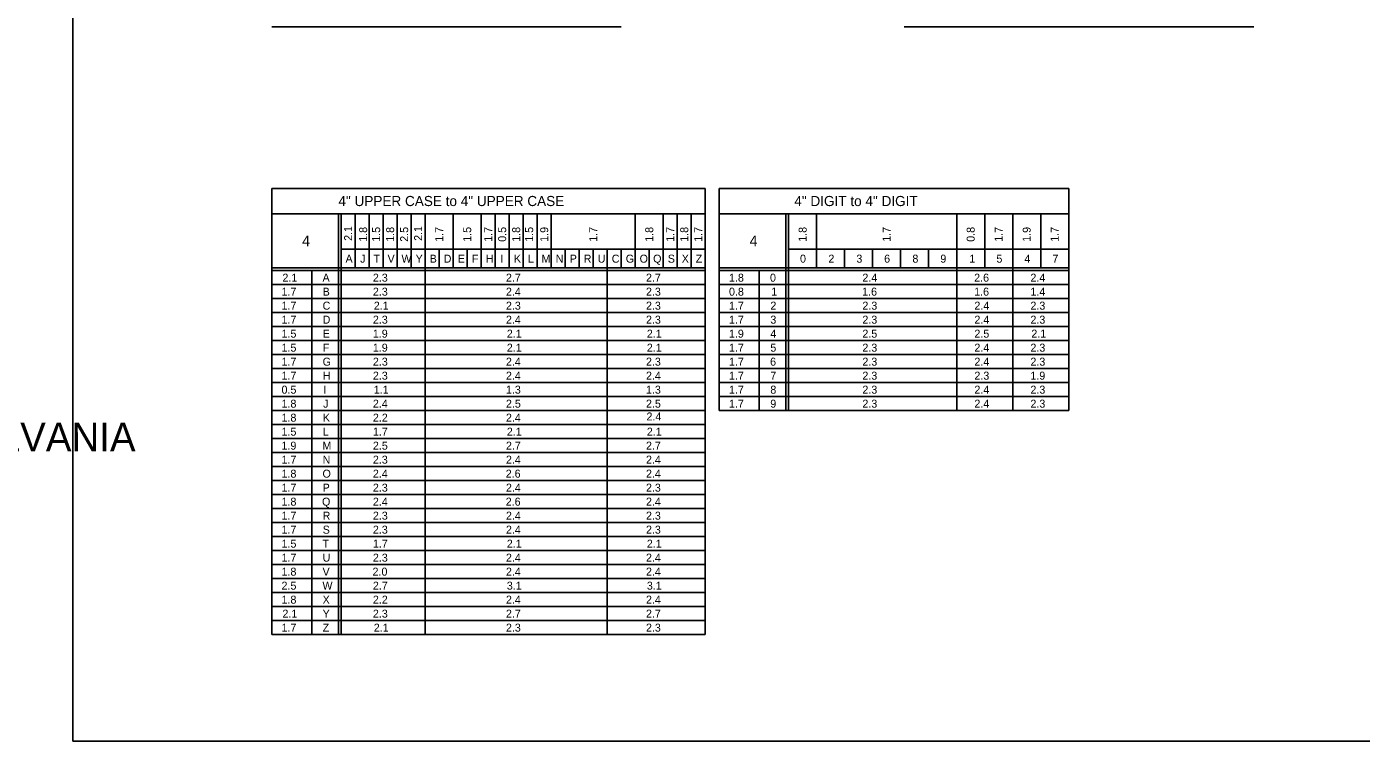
# Model space of a CAD drawing. Extents: x 638421 to 641849, y 297270 to 299646.
# Drawn here: x 640967 to 641467, y 299067 to 299335 of the extents above; entities that cross this region are included whole.
import ezdxf

# ---------------------------------------------------------------- set-up
doc = ezdxf.new("R2010")
doc.units = 0
doc.layers.add('1', color=7, linetype='Continuous')
doc.layers.add('2', color=7, linetype='Continuous')

msp = doc.modelspace()

# ---------------------------------------------------------------- linework, layer by layer
at = {"layer": '1'}
for p, q in [((640984.31, 299630.63), (640984.31, 299066.63)), ((641770.31, 299066.63), (640984.31, 299066.63)), ((640984.31, 299066.63), (641570.31, 299066.63))]:
    msp.add_line(p, q, dxfattribs=at)
at = {"layer": '2'}
for p, q in [((641058.94, 299334.63), (641189.94, 299334.63)), ((641296.06, 299334.63), (641427.06, 299334.63)), ((641221.44, 299274), (641058.94, 299274)), ((641058.94, 299274), (641058.94, 299106.63)), ((641221.44, 299274), (641221.44, 299106.63)), ((641357.69, 299274), (641226.69, 299274)), ((641226.69, 299274), (641226.69, 299190.63)), ((641357.69, 299190.63), (641357.69, 299274)), ((641058.94, 299264.5), (641221.44, 299264.5)), ((641083.94, 299264.5), (641083.94, 299106.63)), ((641084.94, 299264.5), (641084.94, 299106.63)), ((641090.19, 299264.5), (641090.19, 299244.13)), ((641095.44, 299264.5), (641095.44, 299244.13)), ((641100.69, 299264.5), (641100.69, 299244.13)), ((641105.94, 299264.5), (641105.94, 299244.13)), ((641111.19, 299264.5), (641111.19, 299244.13)), ((641116.44, 299264.5), (641116.44, 299106.63)), ((641126.94, 299264.5), (641126.94, 299244.13)), ((641137.44, 299264.5), (641137.44, 299244.13)), ((641142.69, 299264.5), (641142.69, 299244.13)), ((641147.94, 299264.5), (641147.94, 299244.13)), ((641153.19, 299264.5), (641153.19, 299244.13)), ((641158.44, 299264.5), (641158.44, 299244.13)), ((641163.69, 299264.5), (641163.69, 299244.13)), ((641195.19, 299264.5), (641195.19, 299244.13)), ((641205.69, 299264.5), (641205.69, 299244.13)), ((641210.94, 299264.5), (641210.94, 299244.13)), ((641216.19, 299264.5), (641216.19, 299244.13)), ((641226.69, 299264.5), (641357.69, 299264.5)), ((641251.69, 299264.5), (641251.69, 299190.63)), ((641252.69, 299264.5), (641252.69, 299190.63)), ((641263.19, 299264.5), (641263.19, 299244.13)), ((641315.69, 299264.5), (641315.69, 299190.63)), ((641326.19, 299264.5), (641326.19, 299244.13)), ((641336.69, 299264.5), (641336.69, 299190.63)), ((641347.19, 299264.5), (641347.19, 299244.13)), ((641084.94, 299251.13), (641221.44, 299251.13)), ((641121.69, 299251.13), (641121.69, 299244.13)), ((641132.19, 299251.13), (641132.19, 299244.13)), ((641168.94, 299251.13), (641168.94, 299244.13)), ((641174.19, 299251.13), (641174.19, 299244.13)), ((641179.44, 299251.13), (641179.44, 299244.13)), ((641179.44, 299251.13), (641179.44, 299244.13)), ((641184.69, 299251.13), (641184.69, 299106.63)), ((641189.94, 299251.13), (641189.94, 299244.13)), ((641200.44, 299251.13), (641200.44, 299244.13)), ((641252.69, 299251.13), (641357.69, 299251.13)), ((641273.69, 299251.13), (641273.69, 299244.13)), ((641284.19, 299251.13), (641284.19, 299244.13)), ((641294.69, 299251.13), (641294.69, 299244.13)), ((641305.19, 299251.13), (641305.19, 299244.13)), ((641221.44, 299244.13), (641058.94, 299244.13)), ((641357.69, 299244.13), (641226.69, 299244.13)), ((641221.44, 299243.13), (641058.94, 299243.13)), ((641073.94, 299243.13), (641073.94, 299106.63)), ((641357.69, 299243.13), (641226.69, 299243.13)), ((641241.69, 299243.13), (641241.69, 299190.63)), ((641221.44, 299237.88), (641058.94, 299237.88)), ((641357.69, 299237.88), (641226.69, 299237.88)), ((641221.44, 299232.63), (641058.94, 299232.63)), ((641357.69, 299232.63), (641226.69, 299232.63)), ((641221.44, 299227.38), (641058.94, 299227.38)), ((641357.69, 299227.38), (641226.69, 299227.38)), ((641221.44, 299222.13), (641058.94, 299222.13)), ((641357.69, 299222.13), (641226.69, 299222.13)), ((641221.44, 299216.88), (641058.94, 299216.88)), ((641357.69, 299216.88), (641226.69, 299216.88)), ((641221.44, 299211.63), (641058.94, 299211.63)), ((641357.69, 299211.63), (641226.69, 299211.63)), ((641221.44, 299206.38), (641058.94, 299206.38)), ((641357.69, 299206.38), (641226.69, 299206.38)), ((641221.44, 299201.13), (641058.94, 299201.13)), ((641357.69, 299201.13), (641226.69, 299201.13)), ((641221.44, 299195.88), (641058.94, 299195.88)), ((641357.69, 299195.88), (641226.69, 299195.88)), ((641221.44, 299190.63), (641058.94, 299190.63)), ((641226.69, 299190.63), (641357.69, 299190.63)), ((641221.44, 299185.38), (641058.94, 299185.38)), ((641221.44, 299180.13), (641058.94, 299180.13)), ((641221.44, 299174.88), (641058.94, 299174.88)), ((641221.44, 299169.63), (641058.94, 299169.63)), ((641221.44, 299164.38), (641058.94, 299164.38)), ((641221.44, 299159.13), (641058.94, 299159.13)), ((641221.44, 299153.88), (641058.94, 299153.88)), ((641221.44, 299148.63), (641058.94, 299148.63)), ((641221.44, 299143.38), (641058.94, 299143.38)), ((641221.44, 299138.13), (641058.94, 299138.13)), ((641221.44, 299132.88), (641058.94, 299132.88)), ((641221.44, 299127.63), (641058.94, 299127.63)), ((641221.44, 299122.38), (641058.94, 299122.38)), ((641221.44, 299117.13), (641058.94, 299117.13)), ((641221.44, 299111.88), (641058.94, 299111.88)), ((641058.94, 299106.63), (641058.94, 299106.63)), ((641058.94, 299106.63), (641221.44, 299106.63))]:
    msp.add_line(p, q, dxfattribs=at)

# ---------------------------------------------------------------- texts
at = {"layer": '1'}
msp.add_text('COMMONWEALTH OF PENNSYLVANIA', height=10.7828, dxfattribs=at).set_placement((640741.9, 299175.36))
at = {"layer": '2'}
for s, height, p in [('4" UPPER CASE to 4" UPPER CASE', 3.8, (641083.92, 299267.35)), ('4" DIGIT to 4" DIGIT', 3.8, (641254.83, 299267.35)), ('4', 4, (641070.3, 299252.31)), ('4', 4, (641238.05, 299252.31)), ('A', 3, (641086.58, 299246.13)), ('J', 3, (641092.07, 299246.13)), ('T', 3, (641097.07, 299246.13)), ('V', 3, (641102.33, 299246.13)), ('W', 3, (641107.56, 299246.13)), ('Y', 3, (641112.87, 299246.13)), ('B', 3, (641118.13, 299246.13)), ('D', 3, (641123.38, 299246.13)), ('E', 3, (641128.64, 299246.13)), ('F', 3, (641133.95, 299246.13)), ('H', 3, (641139.21, 299246.13)), ('I', 3, (641144.63, 299246.13)), ('K', 3, (641149.71, 299246.13)), ('L', 3, (641154.96, 299246.13)), ('M', 3, (641160.06, 299246.13)), ('N', 3, (641165.38, 299246.13)), ('P', 3, (641170.63, 299246.13)), ('R', 3, (641175.88, 299246.13)), ('U', 3, (641181.12, 299246.13)), ('C', 3, (641186.38, 299246.13)), ('G', 3, (641191.63, 299246.13)), ('O', 3, (641196.83, 299246.13)), ('Q', 3, (641201.9, 299246.13)), ('S', 3, (641207.39, 299246.13)), ('X', 3, (641212.62, 299246.13)), ('Z', 3, (641217.88, 299246.13)), ('0', 3, (641256.96, 299246.13)), ('2', 3, (641267.59, 299246.13)), ('3', 3, (641278.09, 299246.13)), ('6', 3, (641288.5, 299246.13)), ('8', 3, (641299.09, 299246.13)), ('9', 3, (641309.57, 299246.13)), ('1', 3, (641320.43, 299246.13)), ('5', 3, (641330.59, 299246.13)), ('4', 3, (641341.09, 299246.13)), ('7', 3, (641351.59, 299246.13)), ('2.1', 3, (641062.93, 299239)), ('A', 3, (641077.96, 299239)), ('2.3', 3, (641096.84, 299239)), ('2.7', 3, (641146.71, 299239)), ('2.7', 3, (641199.21, 299239)), ('1.8', 3, (641230.34, 299239)), ('0', 3, (641245.71, 299239)), ('2.4', 3, (641280.34, 299239)), ('2.6', 3, (641322.25, 299239)), ('2.4', 3, (641343.34, 299239)), ('1.7', 3, (641062.59, 299233.75)), ('B', 3, (641078, 299233.75)), ('2.3', 3, (641096.84, 299233.75)), ('2.4', 3, (641146.71, 299233.75)), ('2.3', 3, (641199.21, 299233.75)), ('0.8', 3, (641230.34, 299233.75)), ('1', 3, (641246.18, 299233.75)), ('1.6', 3, (641280.25, 299233.75)), ('1.6', 3, (641322.25, 299233.75)), ('1.4', 3, (641343.34, 299233.75)), ('1.7', 3, (641062.59, 299228.5)), ('C', 3, (641078, 299228.5)), ('2.1', 3, (641097.18, 299228.5)), ('2.3', 3, (641146.71, 299228.5)), ('2.3', 3, (641199.21, 299228.5)), ('1.7', 3, (641230.34, 299228.5)), ('2', 3, (641245.84, 299228.5)), ('2.3', 3, (641280.34, 299228.5)), ('2.4', 3, (641322.34, 299228.5)), ('2.3', 3, (641343.34, 299228.5)), ('1.7', 3, (641062.59, 299223.25)), ('D', 3, (641078, 299223.25)), ('2.3', 3, (641096.84, 299223.25)), ('2.4', 3, (641146.71, 299223.25)), ('2.3', 3, (641199.21, 299223.25)), ('1.7', 3, (641230.34, 299223.25)), ('3', 3, (641245.84, 299223.25)), ('2.3', 3, (641280.34, 299223.25)), ('2.4', 3, (641322.34, 299223.25)), ('2.3', 3, (641343.34, 299223.25)), ('1.5', 3, (641062.59, 299218)), ('E', 3, (641078.02, 299218)), ('1.9', 3, (641096.82, 299218)), ('2.1', 3, (641147.05, 299218)), ('2.1', 3, (641199.55, 299218)), ('1.9', 3, (641230.32, 299218)), ('4', 3, (641245.84, 299218)), ('2.5', 3, (641280.34, 299218)), ('2.5', 3, (641322.34, 299218)), ('2.1', 3, (641343.68, 299218)), ('1.5', 3, (641062.59, 299212.75)), ('F', 3, (641078.07, 299212.75)), ('1.9', 3, (641096.82, 299212.75)), ('2.1', 3, (641147.05, 299212.75)), ('2.1', 3, (641199.55, 299212.75)), ('1.7', 3, (641230.34, 299212.75)), ('5', 3, (641245.84, 299212.75)), ('2.3', 3, (641280.34, 299212.75)), ('2.4', 3, (641322.34, 299212.75)), ('2.3', 3, (641343.34, 299212.75)), ('1.7', 3, (641062.59, 299207.5)), ('G', 3, (641078, 299207.5)), ('2.3', 3, (641096.84, 299207.5)), ('2.4', 3, (641146.71, 299207.5)), ('2.3', 3, (641199.21, 299207.5)), ('1.7', 3, (641230.34, 299207.5)), ('6', 3, (641245.75, 299207.5)), ('2.3', 3, (641280.34, 299207.5)), ('2.4', 3, (641322.34, 299207.5)), ('2.3', 3, (641343.34, 299207.5)), ('1.7', 3, (641062.59, 299202.25)), ('H', 3, (641078.09, 299202.25)), ('2.3', 3, (641096.84, 299202.25)), ('2.4', 3, (641146.71, 299202.25)), ('2.4', 3, (641199.21, 299202.25)), ('1.7', 3, (641230.34, 299202.25)), ('7', 3, (641245.84, 299202.25)), ('2.3', 3, (641280.34, 299202.25)), ('2.3', 3, (641322.34, 299202.25)), ('1.9', 3, (641343.32, 299202.25)), ('0.5', 3, (641062.59, 299197)), ('I', 3, (641078.25, 299197)), ('1.1', 3, (641097.18, 299197)), ('1.3', 3, (641146.71, 299197)), ('1.3', 3, (641199.21, 299197)), ('1.7', 3, (641230.34, 299197)), ('8', 3, (641245.84, 299197)), ('2.3', 3, (641280.34, 299197)), ('2.4', 3, (641322.34, 299197)), ('2.3', 3, (641343.34, 299197)), ('1.8', 3, (641062.59, 299191.75)), ('J', 3, (641078.19, 299191.75)), ('2.4', 3, (641096.84, 299191.75)), ('2.5', 3, (641146.71, 299191.75)), ('2.5', 3, (641199.21, 299191.75)), ('1.7', 3, (641230.34, 299191.75)), ('9', 3, (641245.82, 299191.75)), ('2.3', 3, (641280.34, 299191.75)), ('2.4', 3, (641322.34, 299191.75)), ('2.3', 3, (641343.34, 299191.75)), ('1.8', 3, (641062.59, 299186.5)), ('K', 3, (641078.09, 299186.5)), ('2.2', 3, (641096.84, 299186.5)), ('2.4', 3, (641146.71, 299186.5)), ('2.4', 3, (641199.4, 299186.94)), ('1.5', 3, (641062.59, 299181.25)), ('L', 3, (641078.09, 299181.25)), ('1.7', 3, (641096.84, 299181.25)), ('2.1', 3, (641147.05, 299181.25)), ('2.1', 3, (641199.55, 299181.25)), ('1.9', 3, (641062.57, 299176)), ('M', 3, (641077.93, 299176)), ('2.5', 3, (641096.84, 299176)), ('2.7', 3, (641146.71, 299176)), ('2.7', 3, (641199.21, 299176)), ('1.7', 3, (641062.59, 299170.75)), ('N', 3, (641078, 299170.75)), ('2.3', 3, (641096.84, 299170.75)), ('2.4', 3, (641146.71, 299170.75)), ('2.4', 3, (641199.21, 299170.75)), ('1.8', 3, (641062.59, 299165.5)), ('O', 3, (641077.96, 299165.5)), ('2.4', 3, (641096.84, 299165.5)), ('2.6', 3, (641146.63, 299165.5)), ('2.4', 3, (641199.21, 299165.5)), ('1.7', 3, (641062.59, 299160.25)), ('P', 3, (641078, 299160.25)), ('2.3', 3, (641096.84, 299160.25)), ('2.4', 3, (641146.71, 299160.25)), ('2.3', 3, (641199.21, 299160.25)), ('1.8', 3, (641062.59, 299155)), ('Q', 3, (641077.78, 299155)), ('2.4', 3, (641096.84, 299155)), ('2.6', 3, (641146.63, 299155)), ('2.4', 3, (641199.21, 299155)), ('1.7', 3, (641062.59, 299149.75)), ('R', 3, (641078, 299149.75)), ('2.3', 3, (641096.84, 299149.75)), ('2.4', 3, (641146.71, 299149.75)), ('2.3', 3, (641199.21, 299149.75)), ('1.7', 3, (641062.59, 299144.5)), ('S', 3, (641078.02, 299144.5)), ('2.3', 3, (641096.84, 299144.5)), ('2.4', 3, (641146.71, 299144.5)), ('2.3', 3, (641199.21, 299144.5)), ('1.5', 3, (641062.59, 299139.25)), ('T', 3, (641077.94, 299139.25)), ('1.7', 3, (641096.84, 299139.25)), ('2.1', 3, (641147.05, 299139.25)), ('2.1', 3, (641199.55, 299139.25)), ('1.7', 3, (641062.59, 299134)), ('U', 3, (641077.99, 299134)), ('2.3', 3, (641096.84, 299134)), ('2.4', 3, (641146.71, 299134)), ('2.4', 3, (641199.21, 299134)), ('1.8', 3, (641062.59, 299128.75)), ('V', 3, (641077.96, 299128.75)), ('2.0', 3, (641096.71, 299128.75)), ('2.4', 3, (641146.71, 299128.75)), ('2.4', 3, (641199.21, 299128.75)), ('2.5', 3, (641062.59, 299123.5)), ('W', 3, (641077.93, 299123.5)), ('2.7', 3, (641096.84, 299123.5)), ('3.1', 3, (641147.05, 299123.5)), ('3.1', 3, (641199.55, 299123.5)), ('1.8', 3, (641062.59, 299118.25)), ('X', 3, (641077.99, 299118.25)), ('2.2', 3, (641096.84, 299118.25)), ('2.4', 3, (641146.71, 299118.25)), ('2.4', 3, (641199.21, 299118.25)), ('2.1', 3, (641062.93, 299113)), ('Y', 3, (641077.99, 299113)), ('2.3', 3, (641096.84, 299113)), ('2.7', 3, (641146.71, 299113)), ('2.7', 3, (641199.21, 299113)), ('1.7', 3, (641062.59, 299107.75)), ('Z', 3, (641078, 299107.75)), ('2.1', 3, (641097.18, 299107.75)), ('2.3', 3, (641146.71, 299107.75)), ('2.3', 3, (641199.21, 299107.75))]:
    msp.add_text(s, height=height, dxfattribs=at).set_placement(p)
for s, p in [('2.1', (641089.06, 299254.31)), ('1.8', (641094.69, 299253.96)), ('1.5', (641099.56, 299253.96)), ('1.8', (641104.81, 299253.96)), ('2.5', (641110.06, 299253.96)), ('2.1', (641115.31, 299254.31)), ('1.7', (641123.19, 299253.96)), ('1.5', (641133.69, 299253.96)), ('1.7', (641141.56, 299253.96)), ('0.5', (641146.81, 299253.96)), ('1.8', (641152.06, 299253.96)), ('1.5', (641156.92, 299253.96)), ('1.9', (641162.56, 299253.95)), ('1.7', (641180.94, 299253.96)), ('1.8', (641201.94, 299253.96)), ('1.7', (641209.81, 299253.96)), ('1.8', (641215.06, 299253.96)), ('1.7', (641220.31, 299253.96)), ('1.8', (641259.44, 299253.96)), ('1.7', (641290.94, 299253.96)), ('0.8', (641322.44, 299253.96)), ('1.7', (641332.94, 299253.96)), ('1.9', (641343.44, 299253.95)), ('1.7', (641353.94, 299253.96))]:
    msp.add_text(s, height=3, rotation=90, dxfattribs=at).set_placement(p)

doc.saveas('drawing.dxf')
